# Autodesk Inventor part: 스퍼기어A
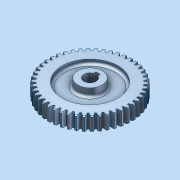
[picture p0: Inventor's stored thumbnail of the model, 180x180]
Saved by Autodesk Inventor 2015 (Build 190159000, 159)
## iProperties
Created: 2024-05
Part Number: 스퍼기어A
Material: 일반
Document SubType Name: Modeling
Designer: Administrator
Density: 1 g/cm^3
Appearance: 기본값
Author: Administrator
Author: jhkim
Creation Date: 2024-05-10
Sending System: Autodesk Inventor 2025
Preprocessor: ST-DEVELOPER v20
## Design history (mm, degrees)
node "스퍼기어A1"
node "솔리드1"
node "기준1"
